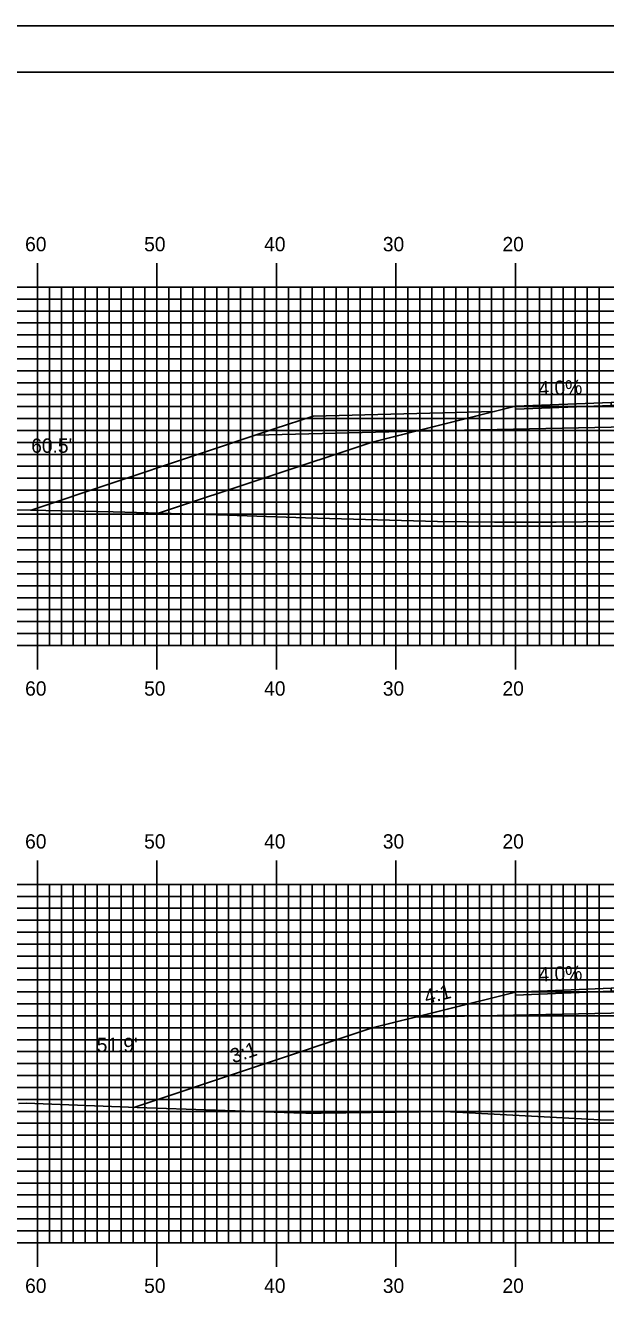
# Model space of a CAD drawing. Extents: x 1807438 to 1807782, y 442591 to 442811.
# Drawn here: x 1807543.3 to 1807591.8, y 442702.5 to 442810.5 of the extents above; entities that cross this region are included whole.
import ezdxf

# ---------------------------------------------------------------- set-up
doc = ezdxf.new("R2010")
doc.units = 0
for name, color, linetype in [('ANNOTATION', 7, 'Continuous'), ('BORDER', 7, 'Continuous'), ('D_Roadway_Centerline', 7, 'Continuous'), ('D_Roadway_Edge_Shoulder', 7, 'Continuous'), ('D_Roadway_SlopeLines', 7, 'Continuous'), ('D_Roadway_SubGrade', 7, 'Continuous'), ('D_Text_Standard', 7, 'Continuous'), ('H_V ANNOTATION', 7, 'Continuous'), ('MAJOR', 7, 'Continuous'), ('MINOR', 7, 'Continuous'), ('PLOT BOUNDARY', 7, 'Continuous'), ('S_Roadway_Centerline', 7, 'Continuous')]:
    doc.layers.add(name, color=color, linetype=linetype)

msp = doc.modelspace()

# ---------------------------------------------------------------- linework, layer by layer
at = {"layer": 'BORDER'}
msp.add_lwpolyline([(1807454.67, 442596.67), (1807774.67, 442596.67), (1807774.67, 442806.67), (1807454.67, 442806.67)], close=True, dxfattribs=at)
at = {"layer": 'D_Roadway_Centerline'}
for points in [[(1807554.39, 442769.74), (1807572.27, 442775.7), (1807575.91, 442776.61), (1807584.27, 442778.7), (1807592.27, 442779.02), (1807604.27, 442779.26), (1807616.27, 442779.02), (1807624.27, 442778.7), (1807632.63, 442776.61), (1807636.27, 442775.7), (1807661.88, 442767.17)], [(1807552.34, 442720), (1807572.27, 442726.65), (1807575.91, 442727.56), (1807584.27, 442729.65), (1807592.27, 442729.97), (1807604.27, 442730.21), (1807616.27, 442729.97), (1807624.27, 442729.65), (1807632.63, 442727.56), (1807636.27, 442726.65), (1807663.15, 442717.69)]]:
    msp.add_lwpolyline(points, dxfattribs=at)
at = {"layer": 'D_Roadway_Edge_Shoulder'}
for points in [[(1807592.27, 442779.02), (1807584.27, 442778.7), (1807584.27, 442778.45), (1807592.27, 442778.77)], [(1807592.27, 442729.97), (1807584.27, 442729.65), (1807584.27, 442729.4), (1807592.27, 442729.72)]]:
    msp.add_lwpolyline(points, close=True, dxfattribs=at)
at = {"layer": 'D_Roadway_SlopeLines'}
for p, q in [((1807582.51, 442778.26), (1807567.33, 442777.88)), ((1807575.91, 442776.61), (1807562.52, 442776.27))]:
    msp.add_line(p, q, dxfattribs=at)
for points in [[(1807584.27, 442778.7), (1807572.27, 442775.7), (1807554.39, 442769.74)], [(1807567.33, 442777.88), (1807564.09, 442776.8), (1807543.75, 442770)], [(1807584.27, 442729.65), (1807572.27, 442726.65), (1807552.34, 442720)]]:
    msp.add_lwpolyline(points, dxfattribs=at)
at = {"layer": 'D_Roadway_SubGrade'}
for points in [[(1807592.27, 442776.94), (1807575.91, 442776.61), (1807584.27, 442778.7), (1807584.27, 442778.45), (1807592.27, 442778.77), (1807604.27, 442779.01), (1807616.27, 442778.77), (1807624.27, 442778.45), (1807624.27, 442778.7), (1807632.63, 442776.61), (1807616.27, 442776.94), (1807604.27, 442777.18)], [(1807592.27, 442727.88), (1807575.91, 442727.56), (1807584.27, 442729.65), (1807584.27, 442729.4), (1807592.27, 442729.72), (1807604.27, 442729.96), (1807616.27, 442729.72), (1807624.27, 442729.4), (1807624.27, 442729.65), (1807632.63, 442727.56), (1807616.27, 442727.88), (1807604.27, 442728.12)]]:
    msp.add_lwpolyline(points, close=True, dxfattribs=at)
at = {"layer": 'MAJOR'}
for p, q in [((1807544.27, 442790.67), (1807544.27, 442788.67)), ((1807554.27, 442790.67), (1807554.27, 442788.67)), ((1807564.27, 442790.67), (1807564.27, 442788.67)), ((1807574.27, 442790.67), (1807574.27, 442788.67)), ((1807584.27, 442790.67), (1807584.27, 442788.67)), ((1807464.27, 442788.67), (1807744.27, 442788.67)), ((1807464.27, 442788.67), (1807744.27, 442788.67)), ((1807544.27, 442758.67), (1807544.27, 442788.67)), ((1807554.27, 442758.67), (1807554.27, 442788.67)), ((1807564.27, 442758.67), (1807564.27, 442788.67)), ((1807574.27, 442758.67), (1807574.27, 442788.67)), ((1807584.27, 442758.67), (1807584.27, 442788.67)), ((1807464.27, 442783.67), (1807744.27, 442783.67)), ((1807464.27, 442778.67), (1807744.27, 442778.67)), ((1807464.27, 442773.67), (1807744.27, 442773.67)), ((1807464.27, 442768.67), (1807744.27, 442768.67)), ((1807464.27, 442763.67), (1807744.27, 442763.67)), ((1807464.27, 442758.67), (1807744.27, 442758.67)), ((1807464.27, 442758.67), (1807744.27, 442758.67)), ((1807544.27, 442756.66), (1807544.27, 442758.67)), ((1807554.27, 442756.66), (1807554.27, 442758.67)), ((1807564.27, 442756.66), (1807564.27, 442758.67)), ((1807574.27, 442756.66), (1807574.27, 442758.67)), ((1807584.27, 442756.66), (1807584.27, 442758.67)), ((1807544.27, 442740.67), (1807544.27, 442738.67)), ((1807554.27, 442740.67), (1807554.27, 442738.67)), ((1807564.27, 442740.67), (1807564.27, 442738.67)), ((1807574.27, 442740.67), (1807574.27, 442738.67)), ((1807584.27, 442740.67), (1807584.27, 442738.67)), ((1807464.27, 442738.67), (1807744.27, 442738.67)), ((1807464.27, 442738.67), (1807744.27, 442738.67)), ((1807544.27, 442708.67), (1807544.27, 442738.67)), ((1807554.27, 442708.67), (1807554.27, 442738.67)), ((1807564.27, 442708.67), (1807564.27, 442738.67)), ((1807574.27, 442708.67), (1807574.27, 442738.67)), ((1807584.27, 442708.67), (1807584.27, 442738.67)), ((1807464.27, 442733.67), (1807744.27, 442733.67)), ((1807464.27, 442728.67), (1807744.27, 442728.67)), ((1807464.27, 442723.67), (1807744.27, 442723.67)), ((1807464.27, 442718.67), (1807744.27, 442718.67)), ((1807464.27, 442713.67), (1807744.27, 442713.67)), ((1807464.27, 442708.67), (1807744.27, 442708.67)), ((1807464.27, 442708.67), (1807744.27, 442708.67)), ((1807544.27, 442706.66), (1807544.27, 442708.67)), ((1807554.27, 442706.66), (1807554.27, 442708.67)), ((1807564.27, 442706.66), (1807564.27, 442708.67)), ((1807574.27, 442706.66), (1807574.27, 442708.67)), ((1807584.27, 442706.66), (1807584.27, 442708.67))]:
    msp.add_line(p, q, dxfattribs=at)
at = {"layer": 'MINOR'}
for p, q in [((1807545.27, 442758.67), (1807545.27, 442788.67)), ((1807546.27, 442758.67), (1807546.27, 442788.67)), ((1807547.27, 442758.67), (1807547.27, 442788.67)), ((1807548.27, 442758.67), (1807548.27, 442788.67)), ((1807549.27, 442758.67), (1807549.27, 442788.67)), ((1807550.27, 442758.67), (1807550.27, 442788.67)), ((1807551.27, 442758.67), (1807551.27, 442788.67)), ((1807552.27, 442758.67), (1807552.27, 442788.67)), ((1807553.27, 442758.67), (1807553.27, 442788.67)), ((1807555.27, 442758.67), (1807555.27, 442788.67)), ((1807556.27, 442758.67), (1807556.27, 442788.67)), ((1807557.27, 442758.67), (1807557.27, 442788.67)), ((1807558.27, 442758.67), (1807558.27, 442788.67)), ((1807559.27, 442758.67), (1807559.27, 442788.67)), ((1807560.27, 442758.67), (1807560.27, 442788.67)), ((1807561.27, 442758.67), (1807561.27, 442788.67)), ((1807562.27, 442758.67), (1807562.27, 442788.67)), ((1807563.27, 442758.67), (1807563.27, 442788.67)), ((1807565.27, 442758.67), (1807565.27, 442788.67)), ((1807566.27, 442758.67), (1807566.27, 442788.67)), ((1807567.27, 442758.67), (1807567.27, 442788.67)), ((1807568.27, 442758.67), (1807568.27, 442788.67)), ((1807569.27, 442758.67), (1807569.27, 442788.67)), ((1807570.27, 442758.67), (1807570.27, 442788.67)), ((1807571.27, 442758.67), (1807571.27, 442788.67)), ((1807572.27, 442758.67), (1807572.27, 442788.67)), ((1807573.27, 442758.67), (1807573.27, 442788.67)), ((1807575.27, 442758.67), (1807575.27, 442788.67)), ((1807576.27, 442758.67), (1807576.27, 442788.67)), ((1807577.27, 442758.67), (1807577.27, 442788.67)), ((1807578.27, 442758.67), (1807578.27, 442788.67)), ((1807579.27, 442758.67), (1807579.27, 442788.67)), ((1807580.27, 442758.67), (1807580.27, 442788.67)), ((1807581.27, 442758.67), (1807581.27, 442788.67)), ((1807582.27, 442758.67), (1807582.27, 442788.67)), ((1807583.27, 442758.67), (1807583.27, 442788.67)), ((1807585.27, 442758.67), (1807585.27, 442788.67)), ((1807586.27, 442758.67), (1807586.27, 442788.67)), ((1807587.27, 442758.67), (1807587.27, 442788.67)), ((1807588.27, 442758.67), (1807588.27, 442788.67)), ((1807589.27, 442758.67), (1807589.27, 442788.67)), ((1807590.27, 442758.67), (1807590.27, 442788.67)), ((1807591.27, 442758.67), (1807591.27, 442788.67)), ((1807464.27, 442787.67), (1807744.27, 442787.67)), ((1807464.27, 442786.67), (1807744.27, 442786.67)), ((1807464.27, 442785.67), (1807744.27, 442785.67)), ((1807464.27, 442784.67), (1807744.27, 442784.67)), ((1807464.27, 442782.67), (1807744.27, 442782.67)), ((1807464.27, 442781.67), (1807744.27, 442781.67)), ((1807464.27, 442780.67), (1807744.27, 442780.67)), ((1807464.27, 442779.67), (1807744.27, 442779.67)), ((1807464.27, 442777.67), (1807744.27, 442777.67)), ((1807464.27, 442776.67), (1807744.27, 442776.67)), ((1807464.27, 442775.67), (1807744.27, 442775.67)), ((1807464.27, 442774.67), (1807744.27, 442774.67)), ((1807464.27, 442772.67), (1807744.27, 442772.67)), ((1807464.27, 442771.67), (1807744.27, 442771.67)), ((1807464.27, 442770.67), (1807744.27, 442770.67)), ((1807464.27, 442769.67), (1807744.27, 442769.67)), ((1807464.27, 442767.67), (1807744.27, 442767.67)), ((1807464.27, 442766.67), (1807744.27, 442766.67)), ((1807464.27, 442765.67), (1807744.27, 442765.67)), ((1807464.27, 442764.67), (1807744.27, 442764.67)), ((1807464.27, 442762.67), (1807744.27, 442762.67)), ((1807464.27, 442761.67), (1807744.27, 442761.67)), ((1807464.27, 442760.67), (1807744.27, 442760.67)), ((1807464.27, 442759.67), (1807744.27, 442759.67)), ((1807545.27, 442708.67), (1807545.27, 442738.67)), ((1807546.27, 442708.67), (1807546.27, 442738.67)), ((1807547.27, 442708.67), (1807547.27, 442738.67)), ((1807548.27, 442708.67), (1807548.27, 442738.67)), ((1807549.27, 442708.67), (1807549.27, 442738.67)), ((1807550.27, 442708.67), (1807550.27, 442738.67)), ((1807551.27, 442708.67), (1807551.27, 442738.67)), ((1807552.27, 442708.67), (1807552.27, 442738.67)), ((1807553.27, 442708.67), (1807553.27, 442738.67)), ((1807555.27, 442708.67), (1807555.27, 442738.67)), ((1807556.27, 442708.67), (1807556.27, 442738.67)), ((1807557.27, 442708.67), (1807557.27, 442738.67)), ((1807558.27, 442708.67), (1807558.27, 442738.67)), ((1807559.27, 442708.67), (1807559.27, 442738.67)), ((1807560.27, 442708.67), (1807560.27, 442738.67)), ((1807561.27, 442708.67), (1807561.27, 442738.67)), ((1807562.27, 442708.67), (1807562.27, 442738.67)), ((1807563.27, 442708.67), (1807563.27, 442738.67)), ((1807565.27, 442708.67), (1807565.27, 442738.67)), ((1807566.27, 442708.67), (1807566.27, 442738.67)), ((1807567.27, 442708.67), (1807567.27, 442738.67)), ((1807568.27, 442708.67), (1807568.27, 442738.67)), ((1807569.27, 442708.67), (1807569.27, 442738.67)), ((1807570.27, 442708.67), (1807570.27, 442738.67)), ((1807571.27, 442708.67), (1807571.27, 442738.67)), ((1807572.27, 442708.67), (1807572.27, 442738.67)), ((1807573.27, 442708.67), (1807573.27, 442738.67)), ((1807575.27, 442708.67), (1807575.27, 442738.67)), ((1807576.27, 442708.67), (1807576.27, 442738.67)), ((1807577.27, 442708.67), (1807577.27, 442738.67)), ((1807578.27, 442708.67), (1807578.27, 442738.67)), ((1807579.27, 442708.67), (1807579.27, 442738.67)), ((1807580.27, 442708.67), (1807580.27, 442738.67)), ((1807581.27, 442708.67), (1807581.27, 442738.67)), ((1807582.27, 442708.67), (1807582.27, 442738.67)), ((1807583.27, 442708.67), (1807583.27, 442738.67)), ((1807585.27, 442708.67), (1807585.27, 442738.67)), ((1807586.27, 442708.67), (1807586.27, 442738.67)), ((1807587.27, 442708.67), (1807587.27, 442738.67)), ((1807588.27, 442708.67), (1807588.27, 442738.67)), ((1807589.27, 442708.67), (1807589.27, 442738.67)), ((1807590.27, 442708.67), (1807590.27, 442738.67)), ((1807591.27, 442708.67), (1807591.27, 442738.67)), ((1807464.27, 442737.67), (1807744.27, 442737.67)), ((1807464.27, 442736.67), (1807744.27, 442736.67)), ((1807464.27, 442735.67), (1807744.27, 442735.67)), ((1807464.27, 442734.67), (1807744.27, 442734.67)), ((1807464.27, 442732.67), (1807744.27, 442732.67)), ((1807464.27, 442731.67), (1807744.27, 442731.67)), ((1807464.27, 442730.67), (1807744.27, 442730.67)), ((1807464.27, 442729.67), (1807744.27, 442729.67)), ((1807464.27, 442727.67), (1807744.27, 442727.67)), ((1807464.27, 442726.67), (1807744.27, 442726.67)), ((1807464.27, 442725.67), (1807744.27, 442725.67)), ((1807464.27, 442724.67), (1807744.27, 442724.67)), ((1807464.27, 442722.67), (1807744.27, 442722.67)), ((1807464.27, 442721.67), (1807744.27, 442721.67)), ((1807464.27, 442720.67), (1807744.27, 442720.67)), ((1807464.27, 442719.67), (1807744.27, 442719.67)), ((1807464.27, 442717.67), (1807744.27, 442717.67)), ((1807464.27, 442716.67), (1807744.27, 442716.67)), ((1807464.27, 442715.67), (1807744.27, 442715.67)), ((1807464.27, 442714.67), (1807744.27, 442714.67)), ((1807464.27, 442712.67), (1807744.27, 442712.67)), ((1807464.27, 442711.67), (1807744.27, 442711.67)), ((1807464.27, 442710.67), (1807744.27, 442710.67)), ((1807464.27, 442709.67), (1807744.27, 442709.67))]:
    msp.add_line(p, q, dxfattribs=at)
at = {"layer": 'PLOT BOUNDARY'}
msp.add_lwpolyline([(1807438.49, 442590.55), (1807778.49, 442590.55), (1807778.49, 442810.55), (1807438.49, 442810.55)], close=True, dxfattribs=at)
at = {"layer": 'S_Roadway_Centerline'}
for points in [[(1807536.03, 442770.16), (1807544.98, 442769.98), (1807550.6, 442769.85), (1807559.37, 442769.61), (1807566.7, 442769.37), (1807577.74, 442769.05), (1807582.52, 442769), (1807587.66, 442769), (1807594.5, 442769.07), (1807602.27, 442768.53), (1807605.8, 442768.34), (1807608.96, 442768.4), (1807617.43, 442768.75), (1807628, 442767.9), (1807631.85, 442767.74), (1807644.28, 442767.53), (1807651.38, 442767.45), (1807653.36, 442767.39), (1807673.96, 442766.85)], [(1807542.68, 442720.33), (1807543.32, 442720.35), (1807552.61, 442719.99), (1807565.72, 442719.56), (1807566.72, 442719.52), (1807568, 442719.53), (1807578.3, 442719.65), (1807591.34, 442718.95), (1807600.81, 442718.83), (1807608.98, 442718.98), (1807613.27, 442719.04), (1807618.49, 442718.84), (1807624.28, 442718.61), (1807629.43, 442718.5), (1807636.24, 442718.41), (1807646.41, 442718.09), (1807649.13, 442718.02), (1807651.47, 442717.95), (1807668.87, 442717.56)]]:
    msp.add_lwpolyline(points, dxfattribs=at)

# ---------------------------------------------------------------- texts
at = {"layer": 'ANNOTATION'}
for s, rotation, p in [('4.0%', 2.2906, (1807586.22, 442779.58)), ('4.0%', 2.2906, (1807586.22, 442730.53)), ('4:1', 14.0362, (1807576.81, 442728.64)), ('3:1', 18.4348, (1807560.64, 442723.68))]:
    msp.add_text(s, height=1.2, rotation=rotation, dxfattribs=at).set_placement(p)
at = {"layer": 'D_Text_Standard'}
for s, p in [("60.5'", (1807543.75, 442774.8)), ("51.9'", (1807549.23, 442724.63))]:
    msp.add_text(s, height=1.2, dxfattribs=at).set_placement(p)
at = {"layer": 'H_V ANNOTATION'}
for s, p in [('60', (1807543.24, 442791.67)), ('50', (1807553.2, 442791.67)), ('40', (1807563.24, 442791.67)), ('30', (1807573.17, 442791.67)), ('20', (1807583.18, 442791.67)), ('60', (1807543.24, 442754.47)), ('50', (1807553.2, 442754.47)), ('40', (1807563.24, 442754.47)), ('30', (1807573.17, 442754.47)), ('20', (1807583.18, 442754.47)), ('60', (1807543.24, 442741.67)), ('50', (1807553.2, 442741.67)), ('40', (1807563.24, 442741.67)), ('30', (1807573.17, 442741.67)), ('20', (1807583.18, 442741.67)), ('60', (1807543.24, 442704.47)), ('50', (1807553.2, 442704.47)), ('40', (1807563.24, 442704.47)), ('30', (1807573.17, 442704.47)), ('20', (1807583.18, 442704.47))]:
    msp.add_text(s, height=1.2, dxfattribs=at).set_placement(p)

doc.saveas('drawing.dxf')
